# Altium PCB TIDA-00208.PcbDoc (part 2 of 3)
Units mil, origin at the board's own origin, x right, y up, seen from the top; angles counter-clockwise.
Board outline 4724.41 x 3937.01 mil, 4 copper layers (Top Layer, MidLayer1, MidLayer2, Bottom Layer), stack 90 mil thick; 243 components, 132 nets, 667 pads, 234 vias.
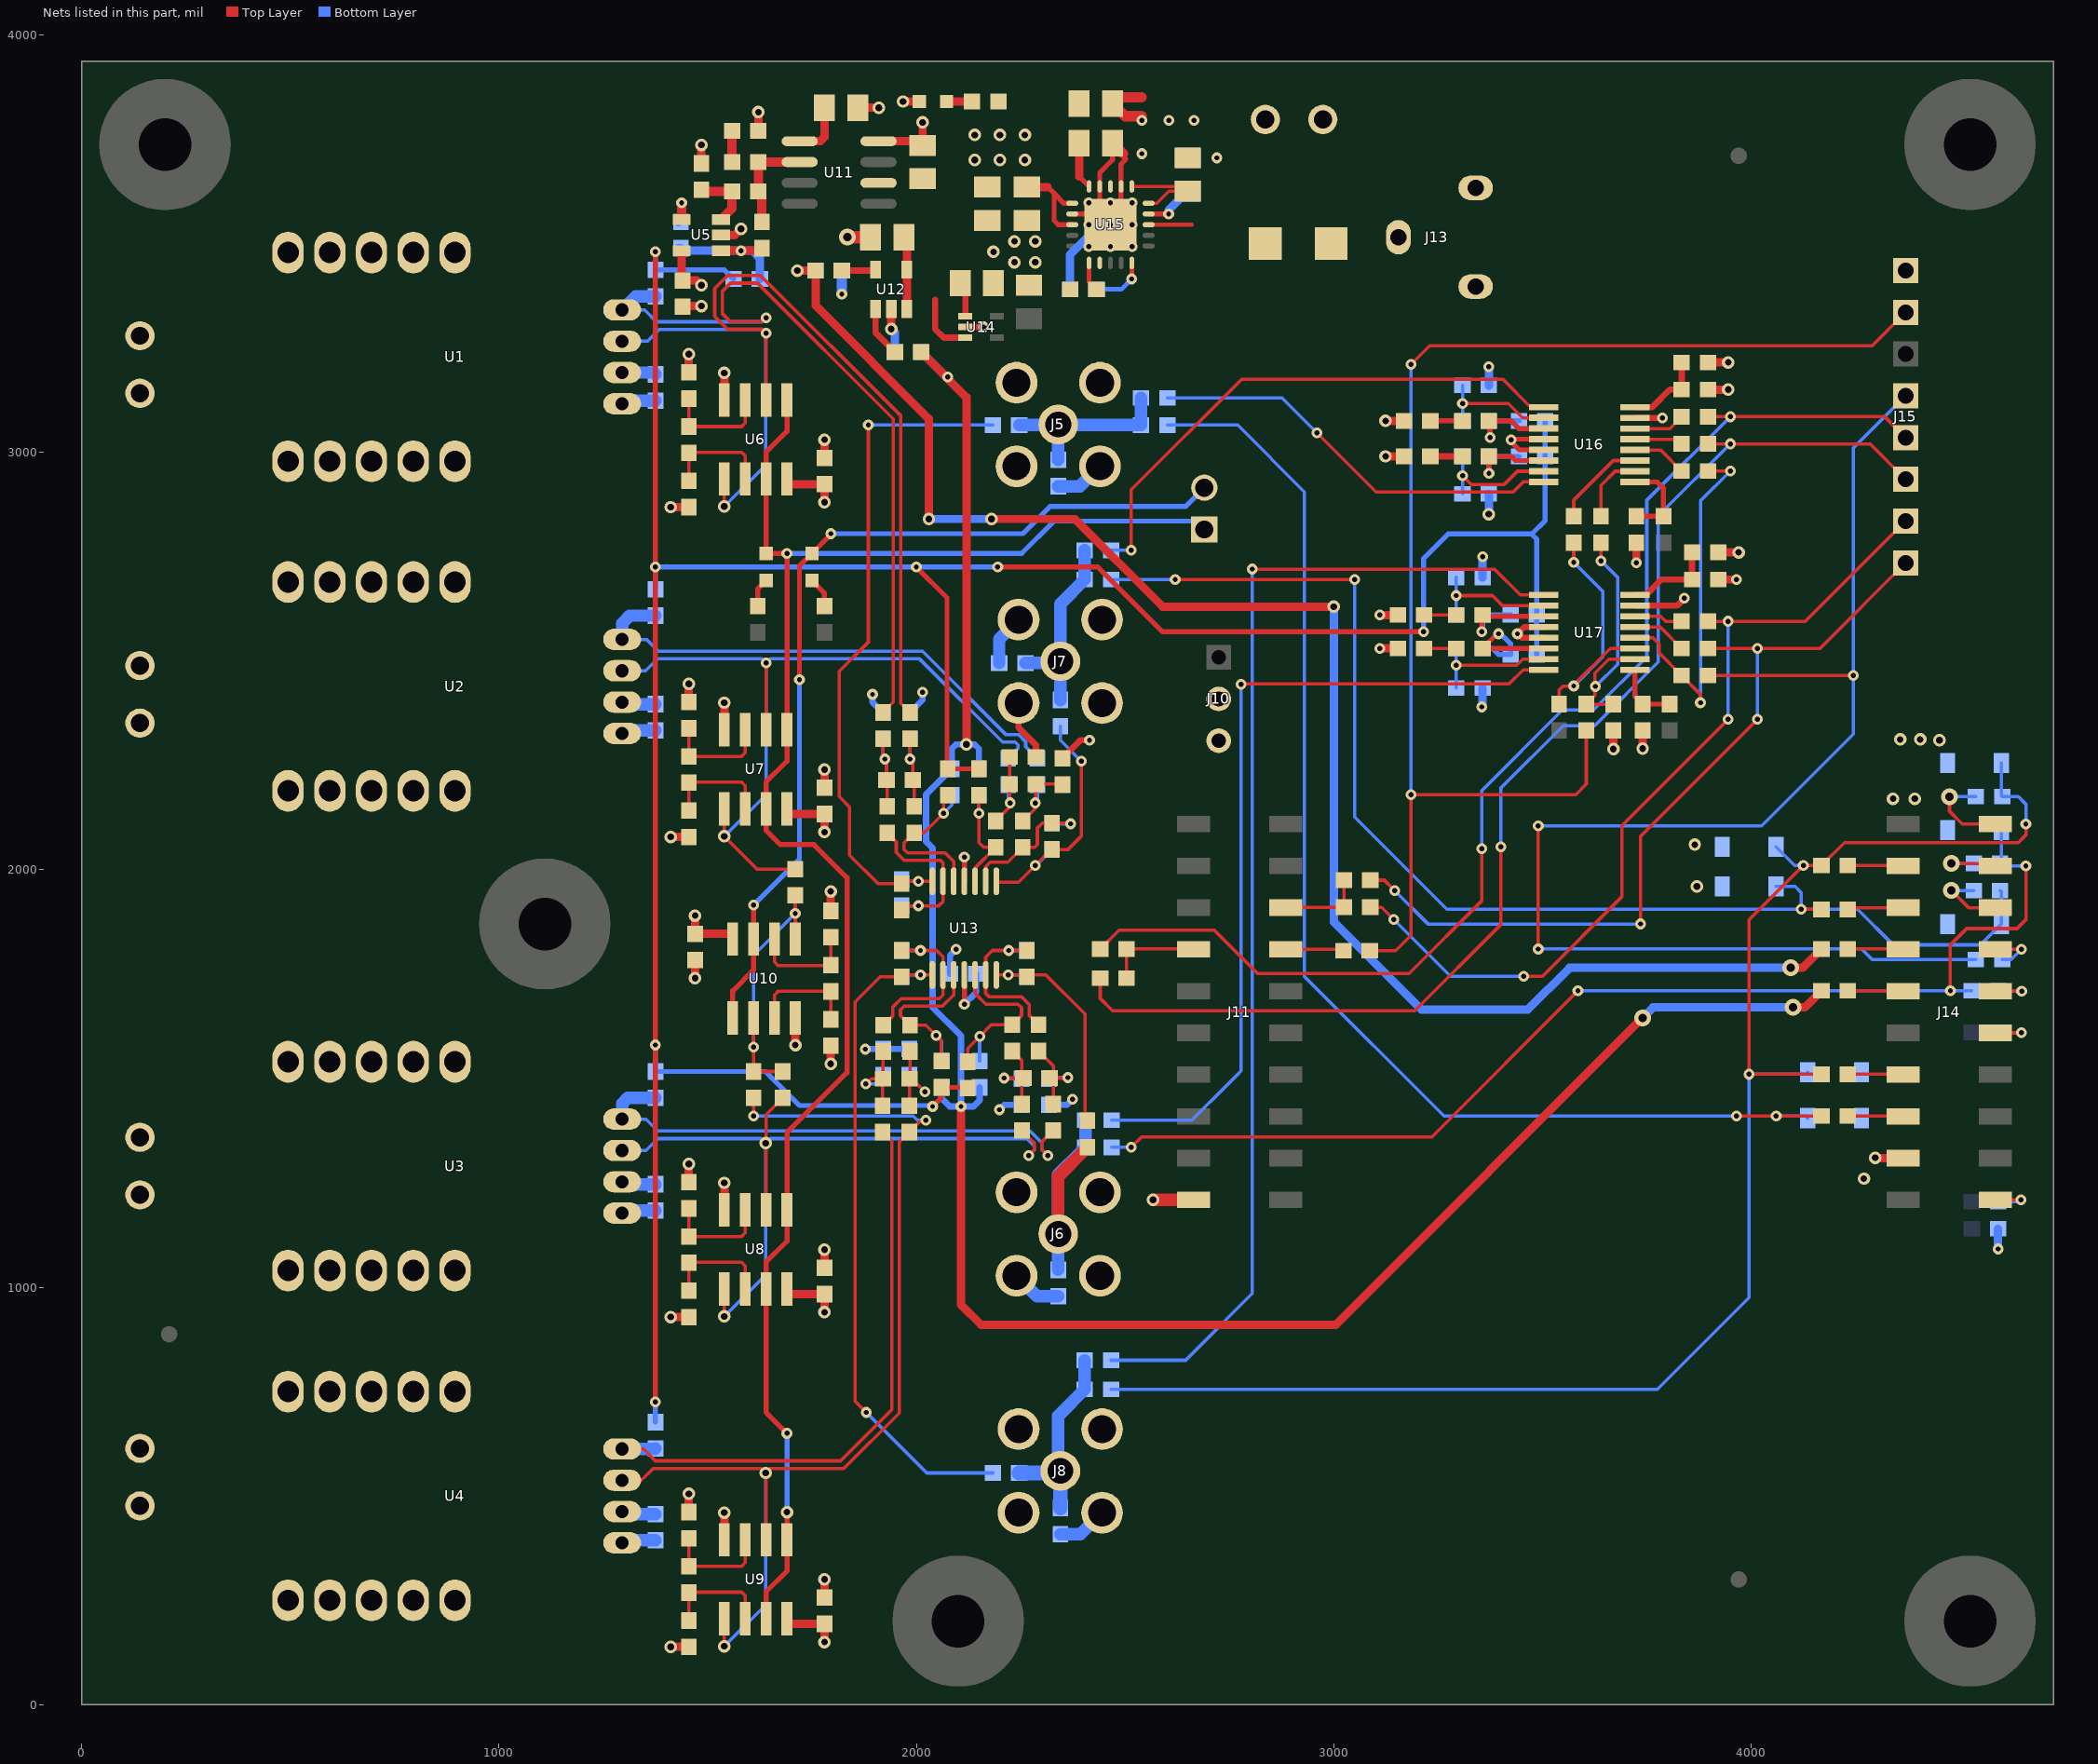
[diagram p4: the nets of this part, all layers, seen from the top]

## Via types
v1: diameter 26, hole 12, Top Layer to Bottom Layer, tented both sides, 143 vias
v2: diameter 30, hole 16, Top Layer to Bottom Layer, tented both sides, 84 vias
v3: diameter 40, hole 20, Top Layer to Bottom Layer, tented both sides, 7 vias

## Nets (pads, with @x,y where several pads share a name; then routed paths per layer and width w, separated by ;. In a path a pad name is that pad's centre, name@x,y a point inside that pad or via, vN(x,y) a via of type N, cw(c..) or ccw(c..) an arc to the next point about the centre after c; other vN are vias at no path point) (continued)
AIN1: D4.1 D5.1 D7.1 R67.2 R71.2 R91.2 R109.1 | length 3890.9
  Top Layer w8: R71.2@4168.5,1510 v1(3995,1510) 3995,1880 v1(4125,2010) R67.2@4168.5,2010 4223.5,2065 4640,2065 4658.15,2083.15 v1(4658.15,2109.05)
  Bottom Layer w8: R91.2@2466.5,755 3775,755 3995,975 v1(3995,1510) 4130.53,1510 D7.1@4135.53,1515 ; D5.1@4059.47,2055 4104.47,2010 v1(4125,2010) ; D4.1@4599.47,2255 4599.47,2177.03 R109.1@4601.5,2175 4640,2175 4658.15,2156.85 v1(4658.15,2109.05)
AIN2: D3.1 R74.1 R93.2 R110.1 | length 2806
  Top Layer w8: v1(2515,1335) 2540,1360 3235,1360 v1(3585,1710) ; v1(4477.2,1710) 4477.2,1820 4516.2,1859 4637,1859 4658.15,1880.15 v1(4658.15,2009.05)
  Bottom Layer w8: R93.2@2467.99,1335 v1(2515,1335) ; v1(3585,1710) R74.1@4528.5,1710 ; D3.1@4599.47,2095 4599.47,2017.97 R110.1@4596.5,2015 4602.44,2009.05 v1(4658.15,2009.05)
AIN3: D2.1 D6.1 R69.1 R89.2 R111.1 | length 3085.9
  Top Layer w8: v1(2620,2695) v1(3050,2695) ; v1(4120,1905) R69.1@4168.5,1905
  Bottom Layer w8: R89.2@2466.5,2695 v1(2620,2695) ; v1(3050,2695) 3050,2126 3271,1905 v1(4120,1905) ; D6.1@4059.47,1960 4105,1960 4120,1945 v1(4120,1905) ; R111.1@4596.5,1950 4599.47,1947.03 D2.1@4599.47,1870 4549.47,1820 4340,1820 4255,1905 v1(4120,1905)
AIN4: D8.1 R72.2 R87.2 | length 3010.2
  Top Layer w8: v1(3965,1410) v1(4060,1410) R72.2@4168.5,1410
  Bottom Layer w8: R87.2@2601.5,3065 2770,3065 2930,2905 2930,1744 3264,1410 v1(3965,1410) ; v1(4060,1410) 4130.53,1410 D8.1@4135.53,1405
AINP_A: R90.2 U17.1 | length 2863.2
  Top Layer w8: v1(2805,2720) 3385,2720 3447,2658 U17.1@3502.7,2658
  Bottom Layer w8: R90.2@2466.5,825 2645,825 2805,985 v1(2805,2720)
AINP_B: R92.2 U17.8 | length 2040
  Top Layer w8: v1(2778,2444) 2771,2444 2770,2445 3420,2445 3453.8,2478.8 U17.8@3502.7,2478.8
  Bottom Layer w8: R92.2@2467.99,1400 2660,1400 2746.5,1486.5 2770,1510 2778,1518 v1(2778,2444)
AINP_C: R88.2 U16.1 | length 1318.7
  Top Layer w8: v1(2515,2765) 2515,2910 2780,3175 3405,3175 3472,3108 U16.1@3502.7,3108
  Bottom Layer w8: R88.2@2466.5,2765 v1(2515,2765)
AINP_D: R86.2 U16.8 | length 1004.3
  Top Layer w8: v1(2960,3046.3) 3101.3,2905 3430,2905 3453.8,2928.8 U16.8@3502.7,2928.8
  Bottom Layer w8: R86.2@2601.5,3130 2876.3,3130 v1(2960,3046.3)
AVDD: C1.2 C2.1 C6.1 C7.1 C8.1 C9.1 C10.1 C12.1 C14.1 C15.2 C16.1 C20.1 C23.1 C24.1 C52.2 C53.2 C54.2 C55.2 R1.2 R4.2 R7.2 R10.2 R24.2 R34.2 R59.2 R63.2 U1.14 U2.14 U3.14 U4.14 U5.5 U6.8 U7.8 U8.8 U9.8 U10.8 U11.2 U12.3 U12.4 U13.4 U14.1 U14.3 U15.1 U15.3 U15.20 | length 2408.4
  Top Layer w12: v1(2115,1678) U13.4@2115,1747.8 ; 2315,3635 2330,3620 ; U15.3@2373.46,3545 2340,3545 2330,3555 2330,3620 ; U15.1@2373.46,3596.18 2353.82,3596.18 2330,3620 ; 2390,3660.35 U15.20@2413.82,3636.54
  Top Layer w15: 2045,3365 2045,3295 2065.59,3274.41 U14.3@2117.6,3274.41 ; C14.1@2105,3405 2117.6,3392.4 U14.1@2117.6,3325.59
  Top Layer w20: U5.5@1437.76,3482.6 1437.76,3413.74 C1.2@1440,3411.5 1473.5,3411.5 v2(1485,3400) ; R10.2@1455,461.5 v2(1455,505) ; R7.2@1455,1251.5 v2(1455,1295) ; R4.2@1455,2401.5 v2(1455,2445) ; R1.2@1455,3191.5 v2(1455,3235) ; v2(1470,1890) C2.1@1470,1846.5 1558.5,1846.5 1560,1845 U10.8@1560,1834 ; U9.8@1690,206 1690,195 1691.5,193.5 C9.1@1780,193.5 v2(1780,150) ; U8.8@1690,996 1690,985 1691.5,983.5 C8.1@1780,983.5 v2(1780,940) ; U7.8@1690,2146 1690,2135 1691.5,2133.5 C7.1@1780,2133.5 v2(1780,2090) ; U6.8@1690,2936 1690,2925 1691.5,2923.5 C6.1@1780,2923.5 v2(1780,2880) ; v2(1795,1535) R24.2@1795,1578.5 ; C10.1@1970,3515 1977.4,3507.6 U12.3@1977.4,3342.76 ; C20.1@2265,3635 2315,3635 ; 2390,3660.35 C24.1@2390,3740 ; R59.2@3896.5,3215 v2(3945,3215) ; R63.2@3921.5,2760 v2(3970,2760)
  Bottom Layer w15: v1(2115,1678) 2143.5,1706.5 C15.2@2143.5,1751
  Bottom Layer w30: U4.14@1295.2,387.5 1301.2,393.5 C55.2@1375,393.5 ; U3.14@1295.2,1177.5 1301.2,1183.5 C54.2@1375,1183.5 ; U2.14@1295.2,2326.48 1302.22,2333.5 C53.2@1375,2333.5 ; U1.14@1295.2,3115.85 1302.85,3123.5 C52.2@1375,3123.5
  other v2: 2140,3700 2200,3700 2260,3700 2140,3760 2200,3760 2260,3760
CS_1: R52.1 R53.1 U17.11 | length 656.1
  Top Layer w8: R52.1@3540,2396.5 3540,2430 3550,2440 v1(3575,2440) 3575,2442.63 3662.27,2529.9 U17.11@3721.7,2529.9 ; v1(3575,2736.5) R53.1@3575,2780
  Bottom Layer w8: v1(3575,2440) 3645,2510 3645,2666.5 v1(3575,2736.5)
GND: C1.1 C2.2 C3.1 C4.2 C5.2 C6.2 C7.2 C8.2 C9.2 C10.2 C12.2 C14.2 C15.1 C16.2 C19.2 C20.2 C21.2 C22.2 C23.2 C24.2 C25.2 C26.2 C27.1 C28.2 C29.1 C30.2 C31.2 C32.2 C33.2 C34.2 C35.1 C36.2 C37.2 C38.2 C39.2 C42.2 C43.2 C44.1 C45.2 C46.2 C49.2 C50.2 C51.1 C52.1 C53.1 C54.1 C55.1 D2.2 D3.2 D4.2 D5.2 D6.2 D7.2 D8.2 J5.2 J5.3 J5.4 J5.5 J6.2 J6.3 J6.4 J6.5 J7.2 J7.3 J7.4 J7.5 J8.2 J8.3 J8.4 J8.5 J10.2 J10.3 J11.19 J12.2 J13.2 J13.3 J14.17 J15.8 LD3.1 R3.1 R6.1 R9.1 R12.1 R22.1 R44.1 R56.1 R77.2 R80.2 R81.2 R84.2 R85.2 U1.13 U2.13 U3.13 U4.13 U5.2 U6.4 U7.4 U8.4 U9.4 U10.4 U11.4 U12.2 U13.11 U14.2 U15.2 U15.7 U15.17 U15.18 U15.19 U15.21 U16.4 U16.5 U16.15 U17.4 U17.5 U17.15 | length 5041.4
  Top Layer w12: U13.11@2115,1972.2 2115,2025 2120,2030 v1(2115,2030) ; U15.2@2373.46,3570.59 2439.41,3570.59 U15.19@2439.41,3636.54 2439.41,3669.41 2470,3700 C24.2@2470,3740 ; v1(2465,3545) 2490.59,3570.59 U15.17@2490.59,3636.54 2490.59,3690.59 2502,3702 ; v1(3425,3030) 3425,3025 3444.4,3005.6 U16.5@3502.7,3005.6 ; v1@3431.2,3031.2 U16.4@3502.7,3031.2
  Top Layer w14: U17.5@3502.7,2555.6 3449.4,2555.6 v1(3440,2565) 3456.2,2581.2 U17.4@3502.7,2581.2 ; U16.15@3721.7,3082.3 v1(3787.7,3082.3)
  Top Layer w15: v1(1878,1570) v1@1878,1571 ; U14.2@2117.6,3300 v1(2160.91,3300) ; J7.4@2245,2398.98 2245,2340 2286.5,2298.5 C19.2@2286.5,2270 ; C22.2@2346.5,2270 C22.2@2350,2266.5 2350,2267 2393,2310 v1(2415,2310) ; U17.15@3721.7,2632.3 3822.3,2632.3 v1(3840,2650)
  Top Layer w20: v2(1411.5,138.5) R12.1@1455,138.5 ; v2(1411.5,928.5) R9.1@1455,928.5 ; v2(1411.5,2078.5) R6.1@1455,2078.5 ; v2(1411.5,2868.5) R3.1@1455,2868.5 ; C1.1@1440,3348.5 1441.5,3350 v2(1485,3350) ; v2(1470,1740) C2.2@1470,1783.5 ; C3.1@1485,3691.5 v2(1485,3736) ; U5.2@1532.24,3520 1565,3520 v2(1580,3535) ; U9.4@1540,395 v2(1540,460) ; U8.4@1540,1185 v2(1540,1250) ; U7.4@1540,2335 v2(1540,2400) ; U6.4@1540,3125 v2(1540,3190) ; C4.2@1621.5,3770 v2(1621.5,3814.5) ; v2(1710,1580) U10.4@1710,1645 ; C9.2@1780,256.5 v2(1780,300) ; C8.2@1780,1046.5 v2(1780,1090) ; C7.2@1780,2196.5 v2(1780,2240) ; C6.2@1780,2986.5 v2(1780,3030) ; R22.1@1795,1901.5 v2(1795,1948) ; C5.2@1860,3825 v2(1910,3825) ; U11.4@1909.49,3745 2005,3745 C12.2@2015,3735 v2(2015,3790) ; v2(1940,3295) U12.2@1940,3342.76 ; v2(1968,3840) LD3.1@2007.52,3840 ; v1(3110,2530) C27.1@3153.5,2530 ; v1(3110,2610) C26.2@3153.5,2610 ; v2(3124,2990) C29.1@3168.5,2990 ; v2(3124,3075) C28.2@3168.5,3075 ; v2(3670,2289) R56.1@3670,2333.5 ; v1(3725,2735) C30.2@3725,2783.5 ; v2(3740,2290) C31.2@3740,2333.5 ; C32.2@3896.5,3150 v2(3945,3150) ; C33.2@3921.5,2695 v1(3965,2695) ; v2@4298.15,1309.05 J14.17@4363.91,1309.05
  Top Layer w25: C24.2@2470,3740 2495,3715 ; v1@2540,3805 2500,3805 C23.2@2470,3835 2485,3850 2540,3850
  Top Layer w30: v3(1835,3515) C10.2@1890,3515 ; v2(2567.17,1209.05) J11.19@2639.78,1209.05
  Bottom Layer w15: v1(1878,1570) 1878.5,1570.5 C50.2@1921,1570.5 C46.2@1983,1570.5 ; v1(1895,2420) 1895,2401.5 C49.2@1920,2376.5 ; C45.2@1985,2376.5 2015,2406.5 v1(2015,2425) ; C15.1@2080.5,1751 2080.5,1794.5 v1(2095,1809) ; v1(2199,1425) 2210.5,1436.5 C43.2@2252,1436.5 ; C39.2@2318,1436.5 2360.5,1436.5 v1(2374,1450)
  Bottom Layer w20: v2(1940,3295) 1948.5,3286.5 C44.1@1948.5,3240 ; R85.2@2368.5,3390 2368.5,3473.5 2412.83,3517.83 v1(2412.83,3545) ; v1(3355,2390) 3356.5,2391.5 R84.2@3356.5,2435 ; R81.2@3356.5,2700 v1(3356.5,2750) ; v2(3371.5,2851.5) R80.2@3371.5,2900 ; R77.2@3371.5,3160 v1(3371.5,3205) ; v1(4591.5,1091.5) C34.2@4591.5,1140
  Bottom Layer w25: v1(1821.5,3378.5) C51.1@1821.5,3435
  Bottom Layer w30: U4.13@1295.2,462.5 1301.2,456.5 C55.1@1375,456.5 ; U3.13@1295.2,1252.5 1301.2,1246.5 C54.1@1375,1246.5 ; U2.13@1295.2,2401.48 1300.18,2396.5 C53.1@1375,2396.5 ; U1.13@1295.2,3190.85 1370.65,3190.85 C52.1@1375,3186.5 ; C42.2@2198.5,2495 2198.5,2552.48 J7.5@2245,2598.98 ; J6.4@2240,1027.4 2288.9,978.5 C38.2@2340,978.5 ; C37.2@2340,2918.5 2392.13,2918.5 J5.3@2440,2966.38 ; C36.2@2345,408.5 2393.5,408.5 J8.3@2445,460
  other v1: 2412.84,3492.83 2465,3492.83 2517.17,3492.83 2517.17,3545 2412.83,3597.16 2465,3597.17 2517.16,3597.16 2720,3705 2540,3715 2540,3795 2605,3795 2665,3795
  other v2: 4270,1260 4297.2,1310 3870,1960 3865,2060 4340,2170 4392,2170 4451,2310 4357,2312 4405,2312 2235,3455 2285,3455 2185,3480 2235,3505 2285,3505
GND_FAULT: J9.2 LD2.1 U10.1 U10.7 | length 2197.9
  Top Layer w12: U10.1@1560,1645 1560,1710 1610,1760 U10.7@1610,1834 v1(1610,1915) ; v1(1720,2455) 1720,2727.48 LD2.1@1750,2757.48 1795,2802.48 v1(1795,2805)
  Bottom Layer w12: v1(1610,1915) 1720,2025 v1(1720,2455) ; v1(1795,2805) 2255,2805 2320,2870 2645,2870 J9.2@2690,2915
NetC3_2: C3.2 R14.1 U5.3 | length 148.5
  Top Layer w22: C3.2@1488.5,3625 R14.1@1558.5,3625 1558.5,3583.66 U5.3@1532.24,3557.4
NetC4_1: C4.1 R13.1 | length 75
  Top Layer w22: R13.1@1558.5,3695 C4.1@1558.5,3770
NetC5_1: C5.1 U11.5 | length 133.6
  Top Layer w20: U11.5@1720.51,3745 1770,3745 1780,3755 C5.1@1780,3825
NetC11_1: C11.1 C46.1 R30.2 R113.2 | length 235.8
  Top Layer w8: R30.2@1983,1434.5 1983.5,1434.99 C11.1@1983.5,1499 ; R113.2@1985,1564.5 1985,1500.5 C11.1@1983.5,1499 ; v1(2020.3,1467.72) 1989.02,1499 C11.1@1983.5,1499
  Bottom Layer w8: C46.1@1983,1507.5 1983,1505.02 v1(2020.3,1467.72)
NetC11_2: C11.2 C50.1 R25.2 R112.2 | length 233.5
  Top Layer w8: v1(1879,1487) 1881,1487 1893,1499 C11.2@1920.5,1499 ; R25.2@1919,1434.5 1919,1497.5 C11.2@1920.5,1499 ; R112.2@1921,1564.5 1920.5,1564.01 C11.2@1920.5,1499
  Bottom Layer w8: v1@1883,1483 v1(1879,1487) 1900.5,1487 C50.1@1921,1507.5
NetC13_1: C13.1 C45.1 R31.2 R119.2 | length 204.7
  Top Layer w8: R31.2@1985,2313.5 v1(1985,2265) 1991.5,2258.5 C13.1@1991.5,2215 ; R119.2@1995,2151.5 C13.1@1995,2206.5
  Bottom Layer w8: v1(1985,2265) C45.1@1985,2313.5
NetC13_2: C13.2 C49.1 R26.2 R118.2 | length 209.6
  Top Layer w8: R26.2@1920,2313.5 1920,2270 v1(1925,2265) 1928.5,2261.5 C13.2@1928.5,2215 ; R118.2@1930,2151.5 C13.2@1930,2208.5
  Bottom Layer w8: C49.1@1920,2313.5 1920,2270 v1(1925,2265)
NetC17_1: C17.1 C19.1 R98.2 R117.2 | length 220.6
  Top Layer w8: R117.2@2190,2116.5 2229.25,2155.75 v1(2225,2160) ; v1@2223.5,2161.5 C17.1@2223.5,2205 C19.1@2223.5,2270
  Bottom Layer w8: R98.2@2220,2203.5 2220,2165 v1(2225,2160) v1@2225,2165
NetC17_2: C17.2 C22.1 R95.2 R116.2 | length 211.2
  Top Layer w8: R116.2@2255,2116.5 2285,2146.5 v1(2285,2160) 2286.5,2161.5 C17.2@2286.5,2205 2348.5,2205 C22.1@2350,2203.5
  Bottom Layer w8: v1(2285,2160) 2290,2165 R95.2@2290,2203.5
NetC18_1: C18.1 C39.1 R40.2 R114.2 | length 233
  Top Layer w8: R114.2@2293,1565.5 2328,1530.5 C18.1@2328,1501 ; C18.1@2319.5,1501 C18.1@2328,1501 ; R40.2@2327,1439.5 R40.2@2328,1438.5 C18.1@2328,1501 ; v1(2363,1502) 2363,1501 C18.1@2328,1501
  Bottom Layer w8: C39.1@2318,1500.5 2319.5,1502 v1(2363,1502)
NetC18_2: C18.2 C43.1 R37.2 R115.2 | length 220.7
  Top Layer w8: v1@2215,1501 C18.2@2253,1501 ; R115.2@2230,1565.5 2253,1542.5 C18.2@2253,1501 ; R37.2@2253,1438.5 C18.2@2253,1501 ; C18.2@2256.5,1501 C18.2@2253,1501
  Bottom Layer w8: v1(2210,1501) 2211.5,1499.5 C43.1@2252,1499.5
NetC25_1: C25.1 D1.1 U15.13 U15.15 U15.16 | length 347.5
  Top Layer w8: U15.16@2516.18,3636.54 2638.46,3636.54 C25.1@2650,3625 2605,3625 2576.18,3596.18 U15.15@2556.54,3596.18
  Top Layer w9: U15.13@2556.54,3545 2660,3545
NetC26_1: C26.1 R49.1 | length 77
  Top Layer w8: C26.1@3216.5,2610 R49.1@3293.5,2610
NetC27_2: C27.2 R48.2 | length 77
  Top Layer w8: C27.2@3216.5,2530 R48.2@3293.5,2530
NetC28_1: C28.1 R50.1 | length 77
  Top Layer w12: C28.1@3231.5,3075 R50.1@3308.5,3075
NetC29_2: C29.2 R51.2 | length 77
  Top Layer w15: C29.2@3231.5,2990 R51.2@3308.5,2990
NetC30_1: C30.1 R57.1 U16.9 | length 206.7
  Top Layer w12: U16.9@3721.7,2928.7 3775,2928.7 3790,2913.7 R57.1@3790,2846.5 C30.1@3725,2846.5
NetC31_1: C31.1 R58.1 U17.9 | length 154.8
  Top Layer w12: U17.9@3721.7,2478.7 3721.7,2414.8 C31.1@3740,2396.5 R58.1@3805,2396.5
NetC32_1: C32.1 R59.1 U16.16 | length 194.2
  Top Layer w15: U16.16@3721.7,3108 3763,3108 3805,3150 C32.1@3833.5,3150 R59.1@3833.5,3215
NetC33_1: C33.1 R63.1 U17.16 | length 217.1
  Top Layer w15: U17.16@3721.7,2658 3748,2658 3785,2695 C33.1@3858.5,2695 R63.1@3858.5,2760
NetC35_2: C35.2 U15.14 | length 121.2
  Top Layer w12: U15.14@2556.54,3570.59 v1(2604.41,3570.59)
  Bottom Layer w20: v1(2604.41,3570.59) 2604.41,3579.41 C35.2@2650,3625
NetC36_1: C36.1 J8.1 R90.1 R91.1 R96.2 | length 475.4
  Bottom Layer w30: J8.1@2340,555 2340,691.5 R91.1@2403.5,755 R90.1@2403.5,825
  Bottom Layer w35: R96.2@2246.5,555 2340,555 2345,550 C36.1@2345,471.5
NetC37_1: C37.1 J5.1 R86.1 R87.1 R97.2 | length 441.1
  Bottom Layer w30: R97.2@2246.5,3065 J5.1@2338.62,3065 ; C37.1@2340,2981.5 2340,3063.62 J5.1@2338.62,3065 ; R86.1@2538.5,3130 R87.1@2538.5,3065 J5.1@2338.62,3065
NetC38_1: C38.1 J6.1 R41.2 R92.1 R93.1 | length 608.4
  Top Layer w30: J6.1@2340,1127.4 2340,1265.5 R41.2@2410,1335.5
  Bottom Layer w30: C38.1@2340,1041.5 2340,1270 R93.1@2395,1325 ; R93.1@2405,1335 R92.1@2405,1400
NetC40_1: C40.1 R39.2 R41.1 U13.7 | length 553.4
  Top Layer w8: U13.7@2191.77,1747.8 v1(2220,1747.8) 2310.2,1747.8 2404,1654 R41.1@2404,1398.5
  Bottom Layer w8: v1(2220,1747.8) 2260.71,1747.8 C40.1@2265,1743.5
NetC40_2: C40.2 R39.1 R114.1 U13.6 | length 408.5
  Top Layer w8: R39.1@2265,1806.5 v1(2221.71,1806.5) 2182.5,1806.5 2166.18,1790.18 U13.6@2166.18,1747.8 2166.18,1703.82 2174,1696 2251.46,1696 2270,1677.46 2270,1651.5 R114.1@2293,1628.5
  Bottom Layer w8: v1(2221.71,1806.5) C40.2@2265,1806.5
NetC41_1: C41.1 R38.2 R94.1 U13.8 | length 589.9
  Top Layer w8: U13.8@2191.77,1972.2 2193.98,1970 2245,1970 v1(2285,2010) 2323.5,2048.5 2363.5,2048.5 2395,2080 v1(2395,2260)
  Bottom Layer w8: v1(2285,2010) 2286.5,2010 C41.1@2325,2048.5 ; R94.1@2345,2343.5 2345,2310 v1(2395,2260)
NetC41_2: C41.2 R38.1 R116.1 U13.9 | length 351.6
  Top Layer w8: U13.9@2166.18,1972.2 2166.18,2007.06 2176.79,2017.67 2219.17,2017.67 R116.1@2255,2053.5 2283.5,2053.5 2290,2060 2290,2100 2301.5,2111.5 R38.1@2325,2111.5 2368.5,2111.5 v1(2370,2110)
  Bottom Layer w8: C41.2@2325,2111.5 2326.5,2110 v1(2370,2110)
NetC42_1: C42.1 J7.1 R88.1 R89.1 R94.2 | length 462.3
  Bottom Layer w30: C42.1@2261.5,2495 J7.1@2341.02,2495 ; R94.2@2345,2406.5 J7.1@2345,2498.98 2345,2636.5 R89.1@2403.5,2695 R88.1@2403.5,2765
NetC47_1: C47.1 R29.2 R96.1 U13.1 | length 1616.6
  Top Layer w8: v1(1880,700) 1853,727 1853,1683 1913.5,1743.5 R29.2@1965,1743.5 1969.29,1747.8 v1(2010,1747.8) U13.1@2038.23,1747.8
  Bottom Layer w8: v1(1880,700) 2025,555 R96.1@2183.5,555 ; C47.1@1965,1743.5 1969.29,1747.8 v1(2010,1747.8)
NetC47_2: C47.2 R29.1 R112.1 U13.2 | length 426.6
  Top Layer w8: R112.1@1921,1627.5 1944,1650.5 1944,1671.46 1963.54,1691 2055,1691 2063.82,1699.82 U13.2@2063.82,1747.8 2063.82,1791.18 2048.5,1806.5 v1(2010,1806.5) R29.1@1965,1806.5
  Bottom Layer w8: C47.2@1965,1806.5 v1(2010,1806.5)
NetC48_1: C48.1 R28.2 R97.1 U13.14 | length 1638.6
  Top Layer w8: v1(1885,3065) 1885,2545 1815,2475 1815,2175 1840,2150 1840,2035 1908.5,1966.5 R28.2@1965,1966.5 1970.71,1972.2 v1(2005,1972.2) U13.14@2038.23,1972.2
  Bottom Layer w8: v1(1885,3065) R97.1@2183.5,3065 ; C48.1@1965,1976.5 1969.29,1972.2 v1(2005,1972.2)
NetC48_2: C48.2 R28.1 R118.1 U13.13 | length 415.9
  Top Layer w8: R118.1@1930,2088.5 1952,2066.5 1952,2055 ; 1952,2057 1952,2041.54 1964.27,2029.27 1971.54,2022 1997,2022 2050,2022 2058,2022 2063.82,2016.18 U13.13@2063.82,1972.2 2063.82,1923.82 2053.5,1913.5 v1(2005,1913.5) R28.1@1965,1913.5
  Bottom Layer w8: C48.2@1965,1913.5 v1(2005,1913.5)
NetD1_2: D1.2 J12.1 J13.1
NetJ1_1: J1.1 U1.6 U1.7 U1.8 U1.9 U1.10
NetJ1_2: J1.2 U1.1 U1.2 U1.3 U1.4 U1.5
NetJ2_1: J2.1 U2.6 U2.7 U2.8 U2.9 U2.10
NetJ2_2: J2.2 U2.1 U2.2 U2.3 U2.4 U2.5
NetJ3_1: J3.1 U3.6 U3.7 U3.8 U3.9 U3.10
NetJ3_2: J3.2 U3.1 U3.2 U3.3 U3.4 U3.5
NetJ4_1: J4.1 U4.6 U4.7 U4.8 U4.9 U4.10
NetJ4_2: J4.2 U4.1 U4.2 U4.3 U4.4 U4.5
NetJ11_6: J11.6 R46.2 R47.2 | length 208.3
  Top Layer w8: J11.6@2882.51,1910 J11.6@2885.85,1910 ; J11.6@2884.91,1909.05 J11.6@2885.85,1910 ; R46.2@3024.5,1975 R47.2@3024.5,1910 J11.6@2885.85,1910
NetJ11_7: J11.7 R42.2 R43.2 | length 230.8
  Top Layer w8: R43.2@2503.5,1740 R42.2@2503.5,1810 2662.96,1810 J11.7@2663.91,1809.05
NetJ11_8: J11.8 R45.2 | length 141.2
  Top Layer w8: J11.8@2885.85,1810 J11.8@2884.91,1809.05 3020.45,1809.05 R45.2@3023.5,1806
NetJ14_2: J14.2 R109.2 | length 221.2
  Top Layer w8: v3(4475,2175) 4475,2140 4505.94,2109.05 J14.2@4584.91,2109.05
  Bottom Layer w8: v3(4475,2175) R109.2@4538.5,2175
NetJ14_3: J14.3 R67.1 | length 132.8
  Top Layer w8: R67.1@4231.5,2010 4362.96,2010 J14.3@4363.91,2009.05
NetJ14_4: J14.4 R110.2 | length 160.9
  Top Layer w8: v3(4480,2015) 4578.96,2015 J14.4@4584.91,2009.05
  Bottom Layer w8: v3(4480,2015) R110.2@4533.5,2015
NetJ14_5: J14.5 R69.2 | length 134.1
  Top Layer w8: R69.2@4231.5,1905 4235.55,1909.05 J14.5@4363.91,1909.05
NetJ14_6: J14.6 R111.2 | length 187.4
  Top Layer w8: v3(4480,1950) 4480,1945 4482.5,1947.5 4520.94,1909.05 J14.6@4584.91,1909.05
  Bottom Layer w8: v3(4480,1950) 4480,1945 4485,1950 R111.2@4533.5,1950
NetJ14_7: J14.7 R70.2 | length 132.8
  Top Layer w8: R70.2@4231.5,1810 4362.96,1810 J14.7@4363.91,1809.05
NetJ14_8: J14.8 R76.2 | length 118
  Top Layer w8: J14.8@4584.91,1809.05 v1(4647.2,1809.05)
  Bottom Layer w8: R76.2@4601.5,1785 4623.15,1785 v1(4647.2,1809.05)
NetJ14_9: J14.9 R68.2 | length 132.8
  Top Layer w8: R68.2@4231.5,1710 4362.96,1710 J14.9@4363.91,1709.05
NetJ14_10: J14.10 R74.2 | length 122.1
  Top Layer w8: J14.10@4584.91,1709.05 v1(4648.15,1709.05)
  Bottom Layer w8: R74.2@4589.65,1709.05 R74.2@4591.5,1709.05 ; R74.2@4591.5,1710 4592.44,1709.05 v1(4648.15,1709.05)
NetJ14_12: J14.12 R75.2 | length 117.1
  Top Layer w8: J14.12@4584.91,1609.05 v1@4646.26,1609.05
  Bottom Layer w8: R75.2@4591.5,1610 v1(4647.2,1610)
NetJ14_13: J14.13 R71.1 | length 132.8
  Top Layer w8: R71.1@4231.5,1510 4362.96,1510 J14.13@4363.91,1509.05
NetJ14_15: J14.15 R72.1 | length 132.8
  Top Layer w8: R72.1@4231.5,1410 4362.96,1410 J14.15@4363.91,1409.05
NetJ14_20: J14.20 R73.1 | length 117.8
  Top Layer w8: J14.20@4584.91,1209.05 v1(4646.26,1209.05)
  Bottom Layer w8: R73.1@4591.5,1205 4642.2,1205 v1(4646.26,1209.05)
NetLD1_2: LD1.2 R16.1 | length 69.3
  Top Layer w12: R16.1@1620,2631.5 1620,2672.52 LD1.2@1640,2692.52
NetLD2_2: LD2.2 R21.1 | length 73.4
  Top Layer w12: LD2.2@1750,2692.52 1780,2662.52 R21.1@1780,2631.5
NetLD3_2: LD3.2 R34.1 | length 61
  Top Layer w20: LD3.2@2072.48,3840 R34.1@2133.5,3840
NetR1_1: R1.1 R2.2 U6.3 | length 260.5
  Top Layer w8: R1.1@1455,3128.5 R2.2@1455,3061.5 1581.5,3061.5 1590,3070 U6.3@1590,3125
NetR2_1: R2.1 R3.2 U6.6 | length 260.5
  Top Layer w8: R3.2@1455,2931.5 R2.1@1455,2998.5 ; R2.1@1455,2999.5 1581.5,2999.5 1590,2991 U6.6@1590,2936
NetR4_1: R4.1 R5.2 U7.3 | length 260.5
  Top Layer w8: R4.1@1455,2338.5 R5.2@1455,2271.5 1581.5,2271.5 1590,2280 U7.3@1590,2335
NetR5_1: R5.1 R6.2 U7.6 | length 260.5
  Top Layer w8: R6.2@1455,2141.5 R5.1@1455,2208.5 ; R5.1@1455,2209.5 1581.5,2209.5 1590,2201 U7.6@1590,2146
NetR7_1: R7.1 R8.2 U8.3 | length 260.5
  Top Layer w8: R7.1@1455,1188.5 R8.2@1455,1121.5 1581.5,1121.5 1590,1130 U8.3@1590,1185
NetR8_1: R8.1 R9.2 U8.6 | length 260.5
  Top Layer w8: R9.2@1455,991.5 R8.1@1455,1058.5 ; R8.1@1455,1059.5 1581.5,1059.5 1590,1051 U8.6@1590,996
NetR10_1: R10.1 R11.2 U9.3 | length 260.5
  Top Layer w8: R10.1@1455,398.5 R11.2@1455,331.5 1581.5,331.5 1590,340 U9.3@1590,395
NetR11_1: R11.1 R12.2 U9.6 | length 260.5
  Top Layer w8: R12.2@1455,201.5 R11.1@1455,268.5 ; R11.1@1455,269.5 1581.5,269.5 1590,261 U9.6@1590,206
NetR13_2: R13.2 R14.2 R17.2 U11.6 | length 246
  Top Layer w22: R17.2@1630,3551.5 1630,3616.5 R14.2@1621.5,3625 R13.2@1621.5,3695 U11.6@1720.51,3695
NetR15_2: R15.2 R18.2 R19.2 U10.2 U10.5 | length 664.4
  Top Layer w8: U10.2@1610,1645 v1(1610,1575) R15.2@1610,1516.5 R18.2@1680,1516.5 ; U10.5@1710,1834 v1(1710,1895) R19.2@1710,1938.5
  Bottom Layer w8: v1(1610,1575) 1610,1795 v1(1710,1895)
NetR17_1: R17.1 R103.2 R104.1 U5.1 | length 354.9
  Top Layer w20: U5.1@1532.24,3482.6 v1(1580,3482.6) 1624.09,3482.6 R17.1@1630,3488.5
  Bottom Layer w20: R104.1@1430,3488.5 R104.1@1436,3488.5 1441.91,3482.6 v1(1580,3482.6) 1607.4,3482.6 1625,3465 R103.2@1625,3415
NetR20_2: R20.2 U12.5 | length 78.9
  Top Layer w15: R20.2@1821.5,3435 U12.5@1900.35,3435
NetR22_2: R22.2 R23.1 U10.6 | length 260.5
  Top Layer w8: U10.6@1660,1834 1660,1779 1668.5,1770.5 1795,1770.5 R22.2@1795,1837.5
NetR23_2: R23.2 R24.1 U10.3 | length 260.5
  Top Layer w8: U10.3@1660,1645 1660,1700 1668.5,1708.5 R23.2@1795,1708.5 ; R24.1@1795,1640.5 R23.2@1795,1707.5
NetR27_2: R27.2 U12.1 | length 121.8
  Top Layer w15: U12.1@1902.6,3342.76 1902.6,3285.91 R27.2@1948.5,3240
NetR32_2: R32.2 R102.2 R113.1 U13.3 | length 442.5
  Top Layer w8: R32.2@2060,1541.5 2060,1590 v1(2047,1603) 2022.5,1627.5 R113.1@1985,1627.5 1962,1650.5 1962,1664 1971,1673 2062.46,1673 2089.41,1699.95 U13.3@2089.41,1747.8
  Bottom Layer w8: v1(2047,1603) 2061,1589 R102.2@2061,1541.5
NetR33_2: R33.2 R101.2 R119.1 U13.12 | length 417.5
  Top Layer w8: R33.2@2075,2178.5 2065,2168.5 v1(2065,2135) 2018.5,2088.5 R119.1@1995,2088.5 1970,2063.5 1970,2049 1979,2040 2069,2040 2089.41,2019.59 U13.12@2089.41,1972.2
  Bottom Layer w8: v1(2065,2135) 2085,2155 R101.2@2085,2178.5
NetR35_2: R35.2 R100.2 R117.1 U13.10 | length 303.5
  Top Layer w8: U13.10@2140.59,1972.2 2140.59,2004.09 R117.1@2190,2053.5 2161.5,2053.5 2150,2065 v1(2150,2135) R35.2@2150,2178.5
  Bottom Layer w8: v1(2150,2135) R100.2@2150,2178.5
NetR36_2: R36.2 R99.2 R115.1 U13.5 | length 442
  Top Layer w8: R36.2@2123,1540 2123,1572 v1(2152,1601) 2179.5,1628.5 R115.1@2230,1628.5 2252,1650.5 2252,1670 2244,1678 2166.54,1678 2140.59,1703.95 U13.5@2140.59,1747.8
  Bottom Layer w8: R99.2@2151.54,1541.5 2151.54,1600.54 v1(2152,1601)
NetR44_2: R44.2 U15.6 | length 70.8
  Top Layer w11: U15.6@2413.82,3453.46 2413.82,3407.68 R44.2@2431.5,3390
NetR48_1: R48.1 R83.2 R121.1 U17.6 | length 337.2
  Top Layer w12: v1(3395,2565) 3391.5,2565 R48.1@3356.5,2530 U17.6@3502.7,2530
  Bottom Layer w12: R83.2@3356.5,2530 3379.98,2530 3394.98,2515 R121.1@3423.5,2515 3423.5,2541.5 3400,2565 v1(3395,2565)
NetR49_2: R49.2 R82.2 R120.1 U17.3 | length 296.7
  Top Layer w12: v1(3355,2570) R49.2@3355,2608.5 ; R49.2@3356.5,2610 R49.2@3355,2608.5 ; U17.3@3502.7,2606.8 3356.7,2606.8 R49.2@3355,2608.5
  Bottom Layer w12: v1(3355,2570) 3356.5,2571.5 R82.2@3356.5,2610 R120.1@3423.5,2610
NetR50_2: R50.2 R78.2 R123.1 U16.3 | length 293.7
  Top Layer w12: v1(3375,3035) 3375,3071.5 R50.2@3371.5,3075 3425.02,3075 3443.22,3056.8 U16.3@3502.7,3056.8
  Bottom Layer w12: v1(3375,3035) 3375,3071.5 R78.2@3371.5,3075 R123.1@3443.5,3075
NetR51_1: R51.1 R79.2 R124.1 U16.6 | length 290.8
  Top Layer w12: v1(3372,2949.01) 3371.5,2948.5 R51.1@3371.5,2990 3425,2990 3435,2980 U16.6@3502.7,2980
  Bottom Layer w12: v1(3372,2949.01) 3372,2989.5 R79.2@3371.5,2990 R124.1@3443.5,2990
NetR53_2: R53.2 U16.11 | length 224.5
  Top Layer w8: R53.2@3575,2846.5 3575,2885 3669.9,2979.9 U16.11@3721.7,2979.9
NetR55_2: R55.2 U16.10 | length 169.4
  Top Layer w8: R55.2@3640,2846.5 3640,2920 3674.3,2954.3 U16.10@3721.7,2954.3
NetR60_1: R60.1 U16.14 | length 123.5
  Top Layer w8: U16.14@3721.7,3056.7 3805.2,3056.7 R60.1@3833.5,3085
NetR61_1: R61.1 U16.13 | length 116.4
  Top Layer w8: U16.13@3721.7,3031.1 3822.4,3031.1 R61.1@3833.5,3020
NetR62_2: R62.2 U16.12 | length 132.7
  Top Layer w8: U16.12@3721.7,3005.5 3783,3005.5 R62.2@3833.5,2955
NetR64_1: R64.1 U17.14 | length 116.7
  Top Layer w8: U17.14@3721.7,2606.7 3783.3,2606.7 3795,2595 R64.1@3833.5,2595
NetR65_1: R65.1 U17.13 | length 133
  Top Layer w8: U17.13@3721.7,2581.1 3782.4,2581.1 R65.1@3833.5,2530
NetR77_1: R77.1 R78.1 U16.2 | length 293.3
  Top Layer w8: v1(3308.5,3116.5) 3418.5,3116.5 3452.6,3082.4 U16.2@3502.7,3082.4
  Bottom Layer w8: R78.1@3308.5,3075 v1(3308.5,3116.5) R77.1@3308.5,3160
NetR79_1: R79.1 R80.1 U16.7 | length 305.7
  Top Layer w8: v1(3308.5,2943.5) 3329.01,2923 3408.6,2923 3440,2954.4 U16.7@3502.7,2954.4
  Bottom Layer w8: R80.1@3308.5,2900 v1(3308.5,2943.5) R79.1@3308.5,2990
NetR81_1: R81.1 R82.1 U17.2 | length 309.2
  Top Layer w8: v1(3293.5,2656.5) 3380,2656.5 3404.1,2632.4 U17.2@3502.7,2632.4
  Bottom Layer w8: R82.1@3293.5,2610 v1(3293.5,2656.5) R81.1@3293.5,2700
NetR83_1: R83.1 R84.1 U17.7 | length 310.2
  Top Layer w8: v1(3293.5,2490) 3438.54,2490 3452.94,2504.4 U17.7@3502.7,2504.4
  Bottom Layer w8: R84.1@3293.5,2435 v1(3293.5,2490) R83.1@3293.5,2530
NetR85_1: R85.1 U15.10 | length 133.5
  Top Layer w11: v1(2516.18,3415) U15.10@2516.18,3453.46
  Bottom Layer w11: R85.1@2431.5,3390 2491.18,3390 v1(2516.18,3415)
NetR104_2: R104.2 U5.4 | length 88.8
  Top Layer w22: U5.4@1437.76,3557.4 v1(1437.76,3597.24)
  Bottom Layer w20: R104.2@1430,3551.5 1437.76,3559.25 v1(1437.76,3597.24)
OC_FAULT: J9.1 LD1.1 U6.1 U6.7 U7.1 U7.7 U8.1 U8.7 U9.1 U9.7 | length 4660.3
  Top Layer w8: U9.7@1640,206 1640,270 ; 1640,700 U8.7@1640,996
  Top Layer w12: U9.7@1640,206 1640,270 1690,320 U9.1@1690,395 v2(1690,461) ; v1(1690,650) 1640,700 U8.7@1640,996 1640,1060 1690,1110 1690,1370 1834,1514 1834,1981 1755,2060 1674.12,2060 1640,2094.12 U7.7@1640,2146 1640,2210 1690,2260 U7.1@1690,2335 v1(1690,2757.48) LD1.1@1640,2757.48 U6.7@1640,2936 1640,3000 1690,3050 U6.1@1690,3125
  Bottom Layer w12: v2(1690,461) v1(1690,650) ; v1(1690,2757.48) 2252.48,2757.48 2330,2835 2670,2835 J9.1@2690,2815
OUT1: R15.1 R30.1 U4.12 U9.2 U9.5 | length 2617.1
  Top Layer w8: U4.12@1295.2,537.5 1341.5,537.5 1370,566 1628,566 v2(1639,555) ; v2(1540,140) U9.5@1540,206 ; v1(1610,1410) R15.1@1610,1453.5 ; U9.2@1640,395 1640,554 v2(1639,555) ; v1@2020.5,1393.5 2017.01,1397 2008.5,1397 R30.1@1983,1371.5 1959,1347.5 1959,698.54 1826.46,566 1691.46,566 1650,566 v2(1639,555)
  Bottom Layer w8: v2(1540,140) 1639,239 v2(1639,555) ; v1(1610,1410) 1993,1410 2003,1400 v1@2025,1400
  other v1: 2023,1400
OUT2: R18.1 R37.1 U3.12 U8.2 U8.5 | length 1931
  Top Layer w8: v2(1540,930) U8.5@1540,996 ; U8.2@1640,1185 1640,1413.5 R18.1@1680,1453.5 ; R37.1@2253,1375.5 2283,1345.5 ; v1(2269,1315) 2283,1329 2283,1345.98
  Bottom Layer w8: U3.12@1295.2,1327.5 1352.7,1327.5 1381.2,1356 1628,1356 v2(1639,1345) ; v2(1540,930) 1639,1029 v2(1639,1345) ; v1(2269,1315) 2283,1329 2283,1337.54 2264.54,1356 1650,1356 v2(1639,1345)
OUT3: R19.1 R98.1 U2.12 U7.2 U7.5 | length 1987.4
  Top Layer w8: U7.5@1540,2146 v2(1540,2080) 1618.5,2001.5 R19.1@1710,2001.5 ; U7.2@1640,2335 v1(1640,2495)
  Bottom Layer w8: U2.12@1295.2,2476.48 1351.48,2476.48 1379.98,2504.98 1630.02,2504.98 v1(1640,2495) ; v2(1540,2080) 1640,2180 v1(1640,2495) ; R98.1@2220,2266.5 2244,2290.5 2244,2299 2237,2306 2206.57,2306 2007.6,2504.98 1649.98,2504.98 v1(1640,2495) ; R98.1@2223.2,2262.38 R98.1@2223.2,2268.2
OUT4: R31.1 U1.12 U6.2 U6.5 | length 2566.9
  Top Layer w8: v2(1540,2870) U6.5@1540,2936 ; U6.2@1640,3125 v1(1640,3285) 1630.5,3294.5 1547.54,3294.5 1517,3325.04 1517,3392.46 1547.54,3423 1627,3423 1963,3087 1963,2398.5 R31.1@1985,2376.5
  Bottom Layer w8: U1.12@1295.2,3265.85 1356.5,3265.85 1385,3294.35 1630.65,3294.35 v1(1640,3285) ; v2(1540,2870) 1639,2969 v1@1639,3285
REF203X_REF: C51.2 R20.1 R70.1 | length 3922
  Top Layer w20: v2(1715,3435) R20.1@1758.5,3435 1758.5,3351.5 2030,3080 v2(2030,2840) ; v2(2180,2840) 2380,2840 2590,2630 v2(3000,2630) ; v3(4095,1765) 4123.5,1765 R70.1@4168.5,1810
  Bottom Layer w20: v2(1715,3435) C51.2@1758.5,3435 ; v2(2030,2840) v2(2180,2840) ; v2(3000,2630) 3000,1875 3210,1665 3465,1665 3565,1765 v3(4095,1765)
REF203X_REF/2: C44.2 R27.1 R68.1 R99.1 R100.1 R101.1 R102.1 | length 5168.2
  Top Layer w20: R27.1@2011.5,3240 2120,3131.5 v2(2120,2300) ; v1(2107,1433) 2107,958 2155,910 3005,910 v3(3740,1645) ; v3(4100,1670) 4128.5,1670 R68.1@4168.5,1710
  Bottom Layer w15: R102.1@2061.7,1480.2 2060,1478.5 2060,1453 2080,1433 v1@2105.5,1433 ; R100.1@2150,2241.5 2150,2290 2140,2300 v2(2120,2300) 2095,2300 2085,2290 R101.1@2085,2241.5 2023.54,2180.04 2023.54,2067.46 2039,2052 2039,1670 2107,1602 v1(2107,1433) ; R99.1@2151.54,1478.5 2151.54,1447.54 2137,1433 v1(2107,1433) ; v1@2105.5,1433 2107,1431.5 v1(2107,1433) ; v1@2105.5,1433 v1(2107,1433)
  Bottom Layer w20: C44.2@2011.5,3240 2071.5,3180 v1(2075,3180) ; v3(3740,1645) 3765,1670 v3(4100,1670)
REF_AINA1: R25.1 R108.1 U4.11 | length 1463.3
  Top Layer w8: U4.11@1295.2,612.5 1346.5,612.5 1375,584 1819,584 1941,706 1941,1350 1919.5,1371.5 R25.1@1919,1371.5
  Bottom Layer w30: U4.11@1295.2,612.5 1374,612.5 R108.1@1375,613.5
REF_AINA2: R40.1 R107.1 U3.11 | length 1265.9
  Top Layer w8: v1(2315,1315) 2301,1329 2301,1348.5 R40.1@2328,1375.5
  Bottom Layer w8: U3.11@1295.2,1402.5 1352.5,1402.5 1381,1374 2038.36,1374 2272,1374 2301,1345 2301,1329 v1(2315,1315)
  Bottom Layer w30: U3.11@1295.2,1402.5 1295.2,1440.2 1308.5,1453.5 R107.1@1375,1453.5
REF_AINA3: R95.1 R106.1 U2.11 | length 1246
  Bottom Layer w8: U2.11@1295.2,2551.48 1353.52,2551.48 1382.02,2522.98 2015.05,2522.98 2214.03,2324 2244.46,2324 2262,2306.46 2262,2294.5 R95.1@2290,2266.5
  Bottom Layer w30: U2.11@1295.2,2551.48 1295.2,2590.2 1313.5,2608.5 R106.1@1375,2608.5
REF_AINA4: R26.1 R105.1 U1.11 | length 1890.2
  Top Layer w8: v1(1640,3322) 1630.5,3312.5 1555,3312.5 1535,3332.5 1535,3385 1555,3405 1619.54,3405 1945,3079.54 1945,2401.5 R26.1@1920,2376.5
  Bottom Layer w8: U1.11@1295.2,3340.85 1349.15,3340.85 1377.65,3312.35 1630.35,3312.35 v1(1640,3322)
  Bottom Layer w30: U1.11@1295.2,3340.85 1327.85,3373.5 R105.1@1375,3373.5
SCLK: J15.5 R66.2 R76.1 | length 3410.3
  Top Layer w8: v1(3490,1810) v1(3490,2105) ; R66.2@3896.5,2465 v1(4245,2465)
  Bottom Layer w8: v1(3490,1810) 4265,1810 4290,1785 R76.1@4538.5,1785 ; v1(3490,2105) 4025,2105 4245,2325 4245,2450 4245,3010 J15.5@4370,3135
SCLK_1: R62.1 R66.1 U17.12 | length 883.6
  Top Layer w8: U17.12@3721.7,2555.5 3764.5,2555.5 3780,2540 3780,2518.5 R66.1@3833.5,2465 3878.5,2420 v1(3878.5,2400) ; R62.1@3896.5,2955 v1(3950,2955)
  Bottom Layer w8: v1(3878.5,2400) 3878.5,2883.5 v1(3950,2955)
SDI: J15.7 R45.1 R54.2 | length 3276.5
  Top Layer w8: R45.1@3086.5,1806 3148,1806 3185,1843 v1(3185,2180) 3580,2180 3605,2205 R54.2@3605,2333.5 ; v1(3185,3210) 3230,3255 4290,3255 J15.7@4370,3335
  Bottom Layer w8: v1(3185,2180) v1(3185,3210)
SDI_1: R54.1 R55.1 R56.2 U17.10 | length 640.7
  Top Layer w8: v1(3640,2740) R55.1@3640,2783.5 ; R56.2@3670,2396.5 R54.1@3605,2396.5 3626,2417.5 3626,2471 3659.3,2504.3 U17.10@3721.7,2504.3
  Bottom Layer w8: v1(3627,2439) 3680,2492 3680,2700 v1(3640,2740)
SDO_A_1: J15.1 R46.1 R65.2 | length 2025.4
  Top Layer w8: R46.1@3087.5,1975 3121,1975 v1(3146,1950) ; v1(3735,1870) 3735,2080 v1(4015,2360) ; R65.2@3896.5,2530 v1(4015,2530) 4165,2530 J15.1@4370,2735
  Bottom Layer w8: v1(3146,1950) 3226,1870 v1(3735,1870) ; v1(4015,2360) v1(4015,2530)
SDO_A_2: J15.3 R43.1 R61.2 | length 3038
  Top Layer w8: R43.1@2440.5,1740 2440.5,1691.5 2470,1662 3194,1662 3400,1868 v1(3400,2055) ; R61.2@3896.5,3020 v1(3950,3020) 4285,3020 J15.3@4370,2935
  Bottom Layer w8: v1(3400,2055) 3400,2195 3550,2345 3625,2345 3777.5,2497.5 3777.5,2847.5 v1(3950,3020)
SDO_B_1: J15.2 R47.1 R64.2 | length 2093.1
  Top Layer w8: R47.1@3087.5,1910 3115,1910 v1(3144,1881) ; v1@3455,1740 v1(3455,1745) 3500,1745 3690,1935 3690,2105 v1(3945,2360) ; R64.2@3896.5,2595 v1(3945,2595) 4130,2595 J15.2@4370,2835
  Bottom Layer w8: v1(3144,1881) 3280,1745 v1(3455,1745) ; v1(3945,2360) v1(3945,2595)
SDO_B_2: J15.4 R42.1 R60.2 | length 2991.9
  Top Layer w8: R42.1@2440.5,1810 2485.5,1855 2714,1855 2817.5,1751.5 3180.5,1751.5 3355,1926 v1(3355,2050) ; R60.2@3896.5,3085 v1(3950,3085) 4320,3085 J15.4@4370,3035
  Bottom Layer w8: v1(3355,2050) 3355,2190 3547.5,2382.5 3622.5,2382.5 3750,2510 3750,2885 v1(3950,3085)
VREF_BUF: R32.1 R33.1 R35.1 R36.1 R103.1 R105.2 R106.2 R107.2 R108.2 R120.2 R121.2 R123.2 R124.2 | length 7512.6
  Top Layer w12: v1(1375,725) v1(1375,1580) v1(1375,2725) v1(1375,3480) ; v1(2000,2725) 2073.5,2651.5 2073.5,2241.5 R35.1@2150,2241.5 ; v1(2039,1433) 2060,1454 R32.1@2060,1478.5 ; R32.1@2060,1474 R32.1@2060,1478.5 ; R36.1@2123,1477 2121.5,1478.5 R32.1@2060,1478.5 ; v1(2195,2725) 2435,2725 2590,2570 v1(3215,2570)
  Bottom Layer w12: R108.2@1375,676.5 v1(1375,725) ; v1(1375,1580) R107.2@1375,1516.5 1638.5,1516.5 1720,1435 2037,1435 v1(2039,1433) ; R106.2@1375,2671.5 v1(1375,2725) v1(2000,2725) v1(2195,2725) ; v1(1375,3480) R105.2@1375,3436.5 1540.51,3436.5 R103.1@1562.01,3415 ; v1(3215,2570) 3215,2745 3274,2804 3474,2804 ; R121.2@3486.5,2515 R120.2@3486.5,2610 3486.5,2791.5 3474,2804 ; R123.2@3506.5,3075 R124.2@3506.5,2990 3506.5,2836.5 3474,2804
pads on no net: FID1.1 FID2.1 FID3.1 FID4.1 FID5.1 FID6.1 H1.1 H2.1 H3.1 H4.0 H5.1 H6.1 H7.0 H8.0 H9.0 H10.0 J11.1 J11.2 J11.3 J11.4 J11.5 J11.9 J11.10 J11.11 J11.12 J11.13 J11.14 J11.15 J11.16 J11.17 J11.18 J11.20 J14.1 J14.11 J14.14 J14.16 J14.18 J14.19 LBL1.0 U11.1 U11.3 U11.7 U11.8 U14.4 U15.4 U15.5 U15.8 U15.9 U15.11 U15.12
copper on no net: | length 5200
  Top Layer w7.87: 3630,70 3630,170 ; 3730,70 3730,170 ; 3830,70 3830,170 ; 3530,70 3530,170 3930,170 3930,70 3530,70
  MidLayer1 w7.87: 3630,70 3630,170 ; 3730,70 3730,170 ; 3830,70 3830,170 ; 3530,70 3530,170 3930,170 3930,70 3530,70
  MidLayer2 w7.87: 3630,70 3630,170 ; 3730,70 3730,170 ; 3830,70 3830,170 ; 3530,70 3530,170 3930,170 3930,70 3530,70
  Bottom Layer w7.87: 3630,70 3630,170 ; 3730,70 3730,170 ; 3830,70 3830,170 ; 3530,70 3530,170 3930,170 3930,70 3530,70

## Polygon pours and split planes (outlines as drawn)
GND on Top Layer "Bottom Layer-No Net" (solid, remove dead copper, pour order 94): 2160,3370 2160,3465 2120,3505 2120,3570 2125,3575 2295,3575 2295,3520 2305,3510 2305,3470 2305,3425 2325,3405 2385,3405 2385,3370
GND on Top Layer "Bottom Layer-No Net" (solid, remove dead copper, pour order 60): 2430,3650 2430,3605 2400,3575 2355,3575 2355,3565 2360,3560 2395,3560 2400,3555 2400,3480 2430,3480 2433,3477 2433,3441 2446,3441 2446,3476 2450,3480 2530,3480 2530,3605 2520,3615 2505,3615 2500,3620 2500,3680 2510,3690 2585,3690 2610,3715 2610,3865 2450,3865 2445,3860 2445,3665
NetJ4_2 on Top Layer "Bottom Layer-No Net" (solid, remove dead copper, pour order 77): 120,191.02 75,236.02 75,450 75,500 90,515 185,515 350,350 910,351.02 950,311.02 950,206.02 935,191.02
NetJ4_1 on Top Layer "Bottom Layer-No Net" (solid, remove dead copper, pour order 56): 935,685 920,670 380,670 290,580 75,580 65,590 65,766.02 105,806.02 925,806.02 935,796.02
NetJ3_2 on Top Layer "Bottom Layer-No Net" (solid, remove dead copper, pour order 78): 120,981.02 75,1026.02 75,1240 95,1260 210,1260 325,1141.02 910,1141.02 950,1101.02 950,996.02 935,981.02
NetJ3_1 on Top Layer "Bottom Layer-No Net" (solid, remove dead copper, pour order 62): 935,1506.02 855,1426.02 330,1426.02 225,1320 85,1320 65,1340 65,1556.02 105,1596.02 925,1596.02 935,1586.02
